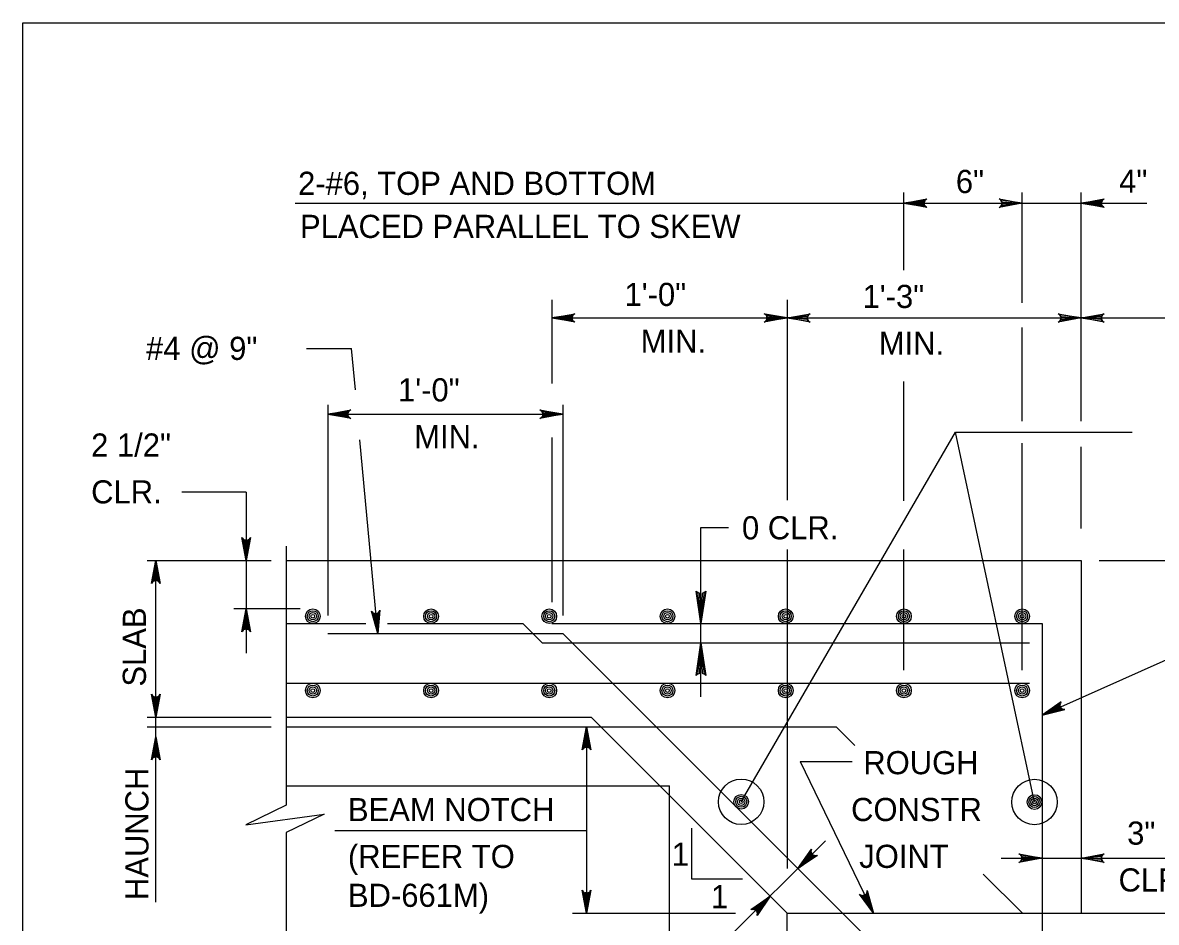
# Model space of a CAD drawing. Extents: x 638653 to 642302, y 298557 to 300414.
# Drawn here: x 639863.2 to 640010, y 299612.9 to 299729.5 of the extents above; entities that cross this region are included whole.
import ezdxf

# ---------------------------------------------------------------- set-up
doc = ezdxf.new("R2010")
doc.units = 0
doc.layers.add('1', color=7, linetype='Continuous')

msp = doc.modelspace()

# ---------------------------------------------------------------- linework, layer by layer
at = {"layer": '1'}
for p, q in [((639863.16, 299165.52), (639863.16, 299729.52)), ((639863.16, 299729.52), (640649.16, 299729.52)), ((639977.33, 299697.45), (639977.33, 299707.5)), ((639992.65, 299693.22), (639992.65, 299707.5)), ((640000.31, 299677.86), (640000.31, 299707.5)), ((639898.47, 299706.12), (640008.81, 299706.12)), ((639931.73, 299693.58), (639931.73, 299682.77)), ((639962.21, 299693.58), (639962.21, 299667.65)), ((639931.73, 299691.25), (639962.21, 299691.25)), ((639962.21, 299691.25), (640000.31, 299691.25)), ((640000.31, 299691.25), (640043.09, 299691.25)), ((639992.65, 299677.86), (639992.65, 299690.01)), ((639899.95, 299687.27), (639905.76, 299687.27)), ((639906.26, 299681.93), (639905.76, 299687.27)), ((639977.33, 299667.55), (639977.33, 299683.03)), ((639902.68, 299679.97), (639902.68, 299652.67)), ((639902.68, 299678.77), (639933.16, 299678.77)), ((639933.16, 299679.97), (639933.16, 299652.67)), ((639931.73, 299675.76), (639931.73, 299654.42)), ((639956.25, 299628.54), (639984.03, 299676.44)), ((639984.03, 299676.44), (640006.89, 299676.44)), ((639994.25, 299628.51), (639984.03, 299676.44)), ((639909.17, 299650.34), (639906.85, 299675.47)), ((639992.65, 299645.6), (639992.65, 299675.01)), ((640000.31, 299663.94), (640000.31, 299674.54)), ((639892.13, 299668.69), (639883.8, 299668.69)), ((639892.13, 299668.69), (639892.13, 299647.79)), ((639951.04, 299642.16), (639951.04, 299664.1)), ((639951.04, 299664.1), (639954.6, 299664.1)), ((639897.28, 299661.67), (639897.28, 299628.08)), ((639962.21, 299661.24), (639962.21, 299619.9)), ((639977.33, 299645.6), (639977.33, 299661.25)), ((639879.3, 299659.83), (639895.34, 299659.83)), ((639880.42, 299639.51), (639880.42, 299659.83)), ((639897.28, 299659.83), (640000.31, 299659.83)), ((640000.31, 299659.83), (640000.31, 299614.11)), ((640002.64, 299659.83), (640021.55, 299659.83)), ((639995.23, 299639.78), (640032.03, 299656.2)), ((639899.13, 299653.54), (639890.52, 299653.54)), ((639897.28, 299651.63), (639907.6, 299651.63)), ((639910.42, 299651.63), (639927.96, 299651.63)), ((639927.96, 299651.63), (639930.47, 299649.12)), ((639931.73, 299651.63), (639995.23, 299651.63)), ((639995.23, 299651.63), (639995.23, 299583.63)), ((639902.68, 299650.34), (639933.16, 299650.34)), ((640005.79, 299577.71), (639933.16, 299650.34)), ((639930.47, 299649.12), (639993.61, 299649.12)), ((639897.28, 299643.91), (639993.61, 299643.91)), ((639879.3, 299639.51), (639895.34, 299639.51)), ((639880.42, 299615.55), (639880.42, 299639.51)), ((639897.28, 299639.51), (639936.81, 299639.51)), ((639962.21, 299614.11), (639936.81, 299639.51)), ((639879.3, 299638.24), (639895.34, 299638.24)), ((639897.28, 299638.24), (639938.08, 299638.24)), ((639936.22, 299638.24), (639936.22, 299614.11)), ((639938.08, 299638.24), (639968.56, 299638.24)), ((639970.97, 299635.82), (639968.56, 299638.24)), ((639963.91, 299633.77), (639973.38, 299614.11)), ((639963.91, 299633.77), (639970.64, 299633.77)), ((639897.28, 299630.62), (639946.97, 299630.62)), ((639946.97, 299546.36), (639946.97, 299630.62)), ((639897.28, 299624.56), (639897.28, 299601.17)), ((639903.6, 299624.82), (639936.22, 299624.82)), ((639949.82, 299625.13), (639949.82, 299618.55)), ((639967.18, 299623.5), (639954.28, 299610.6)), ((639989.93, 299621.24), (640018.92, 299621.24)), ((639949.82, 299618.55), (639956.41, 299618.55)), ((639992.69, 299614.11), (639987.62, 299619.17)), ((639934.38, 299614.11), (639955.53, 299614.11)), ((639962.21, 299614.11), (640000.31, 299614.11)), ((639962.21, 299510.6), (639962.21, 299614.11)), ((640000.31, 299614.11), (640023.17, 299614.11))]:
    msp.add_line(p, q, dxfattribs=at)
for points in [[(639977.33, 299706.12), (639980.32, 299706.68), (639980.2, 299706.6), (639980.09, 299706.52), (639980.03, 299706.42), (639979.97, 299706.32), (639979.95, 299706.22), (639979.93, 299706.12), (639979.95, 299706.02), (639979.97, 299705.92), (639980.03, 299705.82), (639980.09, 299705.72), (639980.2, 299705.64), (639980.32, 299705.56), (639977.33, 299706.12), (639980.2, 299705.64), (639980.09, 299705.72), (639977.33, 299706.12), (639980.03, 299705.82), (639979.97, 299705.92), (639977.33, 299706.12), (639979.95, 299706.02), (639979.93, 299706.12), (639977.33, 299706.12), (639979.95, 299706.22), (639979.97, 299706.32), (639977.33, 299706.12), (639980.03, 299706.42), (639980.09, 299706.52), (639977.33, 299706.12), (639980.2, 299706.6)], [(639992.65, 299706.12), (639989.67, 299705.56), (639989.9, 299705.72), (639990.02, 299705.92), (639990.05, 299706.12), (639990.02, 299706.32), (639989.9, 299706.52), (639989.67, 299706.68), (639992.65, 299706.12), (639989.9, 299706.52), (639990.02, 299706.32), (639992.65, 299706.12), (639990.05, 299706.12), (639990.02, 299705.92), (639992.65, 299706.12), (639989.9, 299705.72)], [(640000.31, 299706.12), (640003.29, 299706.68), (640003.18, 299706.6), (640003.06, 299706.52), (640003, 299706.42), (640002.94, 299706.32), (640002.92, 299706.22), (640002.91, 299706.12), (640002.92, 299706.02), (640002.94, 299705.92), (640003, 299705.82), (640003.06, 299705.72), (640003.18, 299705.64), (640003.29, 299705.56), (640000.31, 299706.12), (640003.18, 299705.64), (640003.06, 299705.72), (640000.31, 299706.12), (640003, 299705.82), (640002.94, 299705.92), (640000.31, 299706.12), (640002.92, 299706.02), (640002.91, 299706.12), (640000.31, 299706.12), (640002.92, 299706.22), (640002.94, 299706.32), (640000.31, 299706.12), (640003, 299706.42), (640003.06, 299706.52), (640000.31, 299706.12), (640003.18, 299706.6)], [(639931.73, 299691.25), (639934.71, 299691.8), (639934.6, 299691.72), (639934.48, 299691.65), (639934.42, 299691.55), (639934.36, 299691.45), (639934.34, 299691.35), (639934.33, 299691.25), (639934.34, 299691.15), (639934.36, 299691.05), (639934.42, 299690.95), (639934.48, 299690.85), (639934.6, 299690.77), (639934.71, 299690.69), (639931.73, 299691.25), (639934.6, 299690.77), (639934.48, 299690.85), (639931.73, 299691.25), (639934.42, 299690.95), (639934.36, 299691.05), (639931.73, 299691.25), (639934.34, 299691.15), (639934.33, 299691.25), (639931.73, 299691.25), (639934.34, 299691.35), (639934.36, 299691.45), (639931.73, 299691.25), (639934.42, 299691.55), (639934.48, 299691.65), (639931.73, 299691.25), (639934.6, 299691.72)], [(639962.21, 299691.25), (639959.22, 299690.69), (639959.34, 299690.77), (639959.45, 299690.85), (639959.51, 299690.95), (639959.57, 299691.05), (639959.59, 299691.15), (639959.61, 299691.25), (639959.59, 299691.35), (639959.57, 299691.45), (639959.51, 299691.55), (639959.45, 299691.65), (639959.34, 299691.72), (639959.22, 299691.8), (639962.21, 299691.25), (639959.34, 299691.72), (639959.45, 299691.65), (639962.21, 299691.25), (639959.51, 299691.55), (639959.57, 299691.45), (639962.21, 299691.25), (639959.59, 299691.35), (639959.61, 299691.25), (639962.21, 299691.25), (639959.59, 299691.15), (639959.57, 299691.05), (639962.21, 299691.25), (639959.51, 299690.95), (639959.45, 299690.85), (639962.21, 299691.25), (639959.34, 299690.77)], [(639962.21, 299691.25), (639965.19, 299691.8), (639964.96, 299691.65), (639964.84, 299691.45), (639964.81, 299691.25), (639964.84, 299691.05), (639964.96, 299690.85), (639965.19, 299690.69), (639962.21, 299691.25), (639964.96, 299690.85), (639964.84, 299691.05), (639962.21, 299691.25), (639964.81, 299691.25), (639964.84, 299691.45), (639962.21, 299691.25), (639964.96, 299691.65)], [(640000.31, 299691.25), (639997.32, 299690.69), (639997.55, 299690.85), (639997.67, 299691.05), (639997.71, 299691.25), (639997.67, 299691.45), (639997.55, 299691.65), (639997.32, 299691.8), (640000.31, 299691.25), (639997.55, 299691.65), (639997.67, 299691.45), (640000.31, 299691.25), (639997.71, 299691.25), (639997.67, 299691.05), (640000.31, 299691.25), (639997.55, 299690.85)], [(640000.31, 299691.25), (640003.29, 299691.8), (640003.06, 299691.65), (640002.94, 299691.45), (640002.91, 299691.25), (640002.94, 299691.05), (640003.06, 299690.85), (640003.29, 299690.69), (640000.31, 299691.25), (640003.06, 299690.85), (640002.94, 299691.05), (640000.31, 299691.25), (640002.91, 299691.25), (640002.94, 299691.45), (640000.31, 299691.25), (640003.06, 299691.65)], [(639902.68, 299678.77), (639905.67, 299679.32), (639905.55, 299679.24), (639905.44, 299679.17), (639905.38, 299679.07), (639905.32, 299678.97), (639905.3, 299678.87), (639905.28, 299678.77), (639905.3, 299678.67), (639905.32, 299678.57), (639905.38, 299678.47), (639905.44, 299678.37), (639905.55, 299678.29), (639905.67, 299678.21), (639902.68, 299678.77), (639905.55, 299678.29), (639905.44, 299678.37), (639902.68, 299678.77), (639905.38, 299678.47), (639905.32, 299678.57), (639902.68, 299678.77), (639905.3, 299678.67), (639905.28, 299678.77), (639902.68, 299678.77), (639905.3, 299678.87), (639905.32, 299678.97), (639902.68, 299678.77), (639905.38, 299679.07), (639905.44, 299679.17), (639902.68, 299678.77), (639905.55, 299679.24)], [(639933.16, 299678.77), (639930.18, 299678.21), (639930.3, 299678.29), (639930.41, 299678.37), (639930.47, 299678.47), (639930.53, 299678.57), (639930.55, 299678.67), (639930.56, 299678.77), (639930.55, 299678.87), (639930.53, 299678.97), (639930.47, 299679.07), (639930.41, 299679.17), (639930.3, 299679.24), (639930.18, 299679.32), (639933.16, 299678.77), (639930.3, 299679.24), (639930.41, 299679.17), (639933.16, 299678.77), (639930.47, 299679.07), (639930.53, 299678.97), (639933.16, 299678.77), (639930.55, 299678.87), (639930.56, 299678.77), (639933.16, 299678.77), (639930.55, 299678.67), (639930.53, 299678.57), (639933.16, 299678.77), (639930.47, 299678.47), (639930.41, 299678.37), (639933.16, 299678.77), (639930.3, 299678.29)], [(639892.13, 299659.83), (639891.57, 299662.81), (639891.65, 299662.69), (639891.73, 299662.58), (639891.83, 299662.52), (639891.93, 299662.46), (639892.03, 299662.44), (639892.13, 299662.43), (639892.23, 299662.44), (639892.33, 299662.46), (639892.43, 299662.52), (639892.53, 299662.58), (639892.61, 299662.69), (639892.69, 299662.81), (639892.13, 299659.83), (639892.61, 299662.69), (639892.53, 299662.58), (639892.13, 299659.83), (639892.43, 299662.52), (639892.33, 299662.46), (639892.13, 299659.83), (639892.23, 299662.44), (639892.13, 299662.43), (639892.13, 299659.83), (639892.03, 299662.44), (639891.93, 299662.46), (639892.13, 299659.83), (639891.83, 299662.52), (639891.73, 299662.58), (639892.13, 299659.83), (639891.65, 299662.69)], [(639880.42, 299659.83), (639880.98, 299656.84), (639880.9, 299656.96), (639880.82, 299657.07), (639880.72, 299657.13), (639880.62, 299657.19), (639880.52, 299657.21), (639880.42, 299657.23), (639880.32, 299657.21), (639880.22, 299657.19), (639880.12, 299657.13), (639880.02, 299657.07), (639879.94, 299656.96), (639879.86, 299656.84), (639880.42, 299659.83), (639879.94, 299656.96), (639880.02, 299657.07), (639880.42, 299659.83), (639880.12, 299657.13), (639880.22, 299657.19), (639880.42, 299659.83), (639880.32, 299657.21), (639880.42, 299657.23), (639880.42, 299659.83), (639880.52, 299657.21), (639880.62, 299657.19), (639880.42, 299659.83), (639880.72, 299657.13), (639880.82, 299657.07), (639880.42, 299659.83), (639880.9, 299656.96)], [(639951.5, 299655.7), (639951.19, 299655.54), (639951.04, 299651.63), (639951.5, 299655.7), (639951.66, 299655.85), (639951.04, 299651.63), (639950.88, 299655.54), (639950.57, 299655.7), (639951.04, 299651.63), (639950.41, 299655.85), (639950.57, 299655.7)], [(639892.13, 299653.54), (639892.69, 299650.56), (639892.61, 299650.67), (639892.53, 299650.79), (639892.43, 299650.85), (639892.33, 299650.91), (639892.23, 299650.92), (639892.13, 299650.94), (639892.03, 299650.92), (639891.93, 299650.91), (639891.83, 299650.85), (639891.73, 299650.79), (639891.65, 299650.67), (639891.57, 299650.56), (639892.13, 299653.54), (639891.65, 299650.67), (639891.73, 299650.79), (639892.13, 299653.54), (639891.83, 299650.85), (639891.93, 299650.91), (639892.13, 299653.54), (639892.03, 299650.92), (639892.13, 299650.94), (639892.13, 299653.54), (639892.23, 299650.92), (639892.33, 299650.91), (639892.13, 299653.54), (639892.43, 299650.85), (639892.53, 299650.79), (639892.13, 299653.54), (639892.61, 299650.67)], [(639909.17, 299650.34), (639908.34, 299653.25), (639908.43, 299653.15), (639908.52, 299653.04), (639908.62, 299652.99), (639908.73, 299652.94), (639908.83, 299652.93), (639908.93, 299652.92), (639909.03, 299652.95), (639909.13, 299652.98), (639909.22, 299653.04), (639909.31, 299653.11), (639909.38, 299653.23), (639909.45, 299653.36), (639909.17, 299650.34), (639909.38, 299653.23), (639909.31, 299653.11), (639909.17, 299650.34), (639909.22, 299653.04), (639909.13, 299652.98), (639909.17, 299650.34), (639909.03, 299652.95), (639908.93, 299652.92), (639909.17, 299650.34), (639908.83, 299652.93), (639908.73, 299652.94), (639909.17, 299650.34), (639908.62, 299652.99), (639908.52, 299653.04), (639909.17, 299650.34), (639908.43, 299653.15)], [(639950.57, 299645.06), (639950.88, 299645.21), (639951.04, 299649.12), (639950.57, 299645.06), (639950.41, 299644.9), (639951.04, 299649.12), (639951.19, 299645.21), (639951.5, 299645.06), (639951.04, 299649.12), (639951.66, 299644.9), (639951.5, 299645.06)], [(639880.42, 299639.51), (639879.86, 299642.49), (639879.94, 299642.37), (639880.02, 299642.26), (639880.12, 299642.2), (639880.22, 299642.14), (639880.32, 299642.12), (639880.42, 299642.11), (639880.52, 299642.12), (639880.62, 299642.14), (639880.72, 299642.2), (639880.82, 299642.26), (639880.9, 299642.37), (639880.98, 299642.49), (639880.42, 299639.51), (639880.9, 299642.37), (639880.82, 299642.26), (639880.42, 299639.51), (639880.72, 299642.2), (639880.62, 299642.14), (639880.42, 299639.51), (639880.52, 299642.12), (639880.42, 299642.11), (639880.42, 299639.51), (639880.32, 299642.12), (639880.22, 299642.14), (639880.42, 299639.51), (639880.12, 299642.2), (639880.02, 299642.26), (639880.42, 299639.51), (639879.94, 299642.37)], [(639995.23, 299639.78), (639998.18, 299640.48), (639998.04, 299640.51), (639997.9, 299640.53), (639997.81, 299640.6), (639997.71, 299640.67), (639997.66, 299640.75), (639997.6, 299640.84), (639997.58, 299640.94), (639997.55, 299641.03), (639997.56, 299641.15), (639997.58, 299641.26), (639997.65, 299641.38), (639997.72, 299641.5), (639995.23, 299639.78), (639997.65, 299641.38), (639997.58, 299641.26), (639995.23, 299639.78), (639997.56, 299641.15), (639997.55, 299641.03), (639995.23, 299639.78), (639997.58, 299640.94), (639997.6, 299640.84), (639995.23, 299639.78), (639997.66, 299640.75), (639997.71, 299640.67), (639995.23, 299639.78), (639997.81, 299640.6), (639997.9, 299640.53), (639995.23, 299639.78), (639998.04, 299640.51)], [(639936.22, 299638.24), (639936.78, 299635.26), (639936.7, 299635.37), (639936.62, 299635.49), (639936.52, 299635.54), (639936.42, 299635.6), (639936.32, 299635.62), (639936.22, 299635.64), (639936.12, 299635.62), (639936.02, 299635.6), (639935.92, 299635.54), (639935.82, 299635.49), (639935.74, 299635.37), (639935.66, 299635.26), (639936.22, 299638.24), (639935.74, 299635.37), (639935.82, 299635.49), (639936.22, 299638.24), (639935.92, 299635.54), (639936.02, 299635.6), (639936.22, 299638.24), (639936.12, 299635.62), (639936.22, 299635.64), (639936.22, 299638.24), (639936.32, 299635.62), (639936.42, 299635.6), (639936.22, 299638.24), (639936.52, 299635.54), (639936.62, 299635.49), (639936.22, 299638.24), (639936.7, 299635.37)], [(639880.42, 299636.97), (639880.98, 299633.98), (639880.9, 299634.1), (639880.82, 299634.21), (639880.72, 299634.27), (639880.62, 299634.33), (639880.52, 299634.35), (639880.42, 299634.37), (639880.32, 299634.35), (639880.22, 299634.33), (639880.12, 299634.27), (639880.02, 299634.21), (639879.94, 299634.1), (639879.86, 299633.98), (639880.42, 299636.97), (639879.94, 299634.1), (639880.02, 299634.21), (639880.42, 299636.97), (639880.12, 299634.27), (639880.22, 299634.33), (639880.42, 299636.97), (639880.32, 299634.35), (639880.42, 299634.37), (639880.42, 299636.97), (639880.52, 299634.35), (639880.62, 299634.33), (639880.42, 299636.97), (639880.72, 299634.27), (639880.82, 299634.21), (639880.42, 299636.97), (639880.9, 299634.1)], [(639897.28, 299628.08), (639892.09, 299625.54), (639902.24, 299626.92), (639897.28, 299624.56)], [(639963.59, 299619.91), (639965.34, 299622.39), (639965.31, 299622.25), (639965.28, 299622.12), (639965.31, 299622), (639965.34, 299621.89), (639965.39, 299621.81), (639965.45, 299621.72), (639965.53, 299621.66), (639965.62, 299621.6), (639965.73, 299621.57), (639965.84, 299621.54), (639965.98, 299621.57), (639966.12, 299621.59), (639963.59, 299619.91), (639965.98, 299621.57), (639965.84, 299621.54), (639963.59, 299619.91), (639965.73, 299621.57), (639965.62, 299621.6), (639963.59, 299619.91), (639965.53, 299621.66), (639965.45, 299621.72), (639963.59, 299619.91), (639965.39, 299621.81), (639965.34, 299621.89), (639963.59, 299619.91), (639965.31, 299622), (639965.28, 299622.12), (639963.59, 299619.91), (639965.31, 299622.25)], [(639995.23, 299621.24), (639992.24, 299620.68), (639992.47, 299620.84), (639992.59, 299621.04), (639992.63, 299621.24), (639992.59, 299621.44), (639992.47, 299621.64), (639992.24, 299621.8), (639995.23, 299621.24), (639992.47, 299621.64), (639992.59, 299621.44), (639995.23, 299621.24), (639992.63, 299621.24), (639992.59, 299621.04), (639995.23, 299621.24), (639992.47, 299620.84)], [(640000.31, 299621.24), (640003.29, 299621.8), (640003.06, 299621.64), (640002.94, 299621.44), (640002.91, 299621.24), (640002.94, 299621.04), (640003.06, 299620.84), (640003.29, 299620.68), (640000.31, 299621.24), (640003.06, 299620.84), (640002.94, 299621.04), (640000.31, 299621.24), (640002.91, 299621.24), (640002.94, 299621.44), (640000.31, 299621.24), (640003.06, 299621.64)], [(639936.22, 299614.11), (639935.66, 299617.09), (639935.74, 299616.97), (639935.82, 299616.86), (639935.92, 299616.8), (639936.02, 299616.74), (639936.12, 299616.72), (639936.22, 299616.71), (639936.32, 299616.72), (639936.42, 299616.74), (639936.52, 299616.8), (639936.62, 299616.86), (639936.7, 299616.97), (639936.78, 299617.09), (639936.22, 299614.11), (639936.7, 299616.97), (639936.62, 299616.86), (639936.22, 299614.11), (639936.52, 299616.8), (639936.42, 299616.74), (639936.22, 299614.11), (639936.32, 299616.72), (639936.22, 299616.71), (639936.22, 299614.11), (639936.12, 299616.72), (639936.02, 299616.74), (639936.22, 299614.11), (639935.92, 299616.8), (639935.82, 299616.86), (639936.22, 299614.11), (639935.74, 299616.97)], [(639973.38, 299614.11), (639971.58, 299616.55), (639971.7, 299616.48), (639971.82, 299616.41), (639971.94, 299616.4), (639972.06, 299616.39), (639972.15, 299616.42), (639972.25, 299616.45), (639972.33, 299616.51), (639972.42, 299616.57), (639972.48, 299616.66), (639972.54, 299616.76), (639972.57, 299616.9), (639972.59, 299617.04), (639973.38, 299614.11), (639972.57, 299616.9), (639972.54, 299616.76), (639973.38, 299614.11), (639972.48, 299616.66), (639972.42, 299616.57), (639973.38, 299614.11), (639972.33, 299616.51), (639972.25, 299616.45), (639973.38, 299614.11), (639972.15, 299616.42), (639972.06, 299616.39), (639973.38, 299614.11), (639971.94, 299616.4), (639971.82, 299616.41), (639973.38, 299614.11), (639971.7, 299616.48)], [(639960, 299616.32), (639958.31, 299613.79), (639958.34, 299613.93), (639958.36, 299614.07), (639958.33, 299614.18), (639958.3, 299614.29), (639958.24, 299614.37), (639958.18, 299614.46), (639958.1, 299614.51), (639958.01, 299614.57), (639957.9, 299614.6), (639957.79, 299614.63), (639957.65, 299614.6), (639957.51, 299614.57), (639960, 299616.32), (639957.65, 299614.6), (639957.79, 299614.63), (639960, 299616.32), (639957.9, 299614.6), (639958.01, 299614.57), (639960, 299616.32), (639958.1, 299614.51), (639958.18, 299614.46), (639960, 299616.32), (639958.24, 299614.37), (639958.3, 299614.29), (639960, 299616.32), (639958.33, 299614.18), (639958.36, 299614.07), (639960, 299616.32), (639958.34, 299613.93)]]:
    msp.add_lwpolyline(points, dxfattribs=at)
for centre, radius in [((639900.75, 299652.59), 0.952), ((639900.75, 299652.59), 0.714), ((639900.75, 299652.59), 0.476), ((639900.75, 299652.59), 0.238), ((639916.07, 299652.59), 0.952), ((639916.07, 299652.59), 0.714), ((639916.07, 299652.59), 0.476), ((639916.07, 299652.59), 0.238), ((639931.38, 299652.59), 0.952), ((639931.38, 299652.59), 0.714), ((639931.38, 299652.59), 0.476), ((639931.38, 299652.59), 0.238), ((639946.7, 299652.59), 0.952), ((639946.7, 299652.59), 0.714), ((639946.7, 299652.59), 0.476), ((639946.7, 299652.59), 0.238), ((639962.02, 299652.59), 0.952), ((639962.02, 299652.59), 0.714), ((639962.02, 299652.59), 0.476), ((639962.02, 299652.59), 0.238), ((639977.33, 299652.59), 0.952), ((639977.33, 299652.59), 0.714), ((639977.33, 299652.59), 0.476), ((639977.33, 299652.59), 0.238), ((639992.65, 299652.59), 0.952), ((639992.65, 299652.59), 0.714), ((639992.65, 299652.59), 0.476), ((639992.65, 299652.59), 0.238), ((639900.75, 299642.96), 0.952), ((639900.75, 299642.96), 0.714), ((639900.75, 299642.96), 0.476), ((639916.07, 299642.96), 0.952), ((639916.07, 299642.96), 0.714), ((639916.07, 299642.96), 0.476), ((639931.38, 299642.96), 0.952), ((639931.38, 299642.96), 0.714), ((639931.38, 299642.96), 0.476), ((639946.7, 299642.96), 0.952), ((639946.7, 299642.96), 0.714), ((639946.7, 299642.96), 0.476), ((639962.02, 299642.96), 0.952), ((639962.02, 299642.96), 0.714), ((639962.02, 299642.96), 0.476), ((639977.33, 299642.96), 0.952), ((639977.33, 299642.96), 0.714), ((639977.33, 299642.96), 0.476), ((639992.65, 299642.96), 0.952), ((639992.65, 299642.96), 0.714), ((639992.65, 299642.96), 0.476), ((639900.75, 299642.96), 0.238), ((639916.07, 299642.96), 0.238), ((639931.38, 299642.96), 0.238), ((639946.7, 299642.96), 0.238), ((639962.02, 299642.96), 0.238), ((639977.33, 299642.96), 0.238), ((639992.65, 299642.96), 0.238), ((639956.25, 299628.54), 2.94), ((639994.25, 299628.51), 2.94), ((639956.25, 299628.54), 0.952), ((639956.25, 299628.54), 0.714), ((639956.25, 299628.54), 0.476), ((639956.25, 299628.54), 0.238), ((639994.25, 299628.51), 0.952), ((639994.25, 299628.51), 0.714), ((639994.25, 299628.51), 0.476), ((639994.25, 299628.51), 0.238)]:
    msp.add_circle(centre, radius, dxfattribs=at)

# ---------------------------------------------------------------- texts
for s, p in [('2-#6, TOP AND BOTTOM', (639898.84, 299707.2)), ('6"', (639984.06, 299707.44)), ('4"', (640005.22, 299707.47)), ('PLACED PARALLEL TO SKEW', (639899.09, 299701.62)), ('1\'-0"', (639941.13, 299692.8)), ('1\'-3"', (639971.97, 299692.54)), ('#4 @ 9"', (639879.15, 299685.81)), ('MIN.', (639943.23, 299686.73)), ('MIN.', (639974.08, 299686.47)), ('1\'-0"', (639911.79, 299680.43)), ('MIN.', (639913.89, 299674.36)), ('2 1/2"', (639872.03, 299673.28)), ('CLR.', (639872.03, 299667.21)), ('0 CLR.', (639956.35, 299662.55)), ('ROUGH', (639972.07, 299632.11)), ('BEAM NOTCH', (639905.3, 299626.03)), ('CONSTR', (639970.49, 299626.04)), (' 3"', (640005.14, 299622.98)), ('(REFER TO', (639905.3, 299619.96)), ('1', (639947.26, 299620.25)), (' JOINT', (639970.43, 299619.97)), ('CLR.', (640005.14, 299616.91)), ('BD-661M)', (639905.3, 299614.92)), ('1', (639952.32, 299614.74))]:
    msp.add_text(s, height=3, dxfattribs=at).set_placement(p)
for s, p in [('SLAB', (639879.13, 299643.47)), ('HAUNCH', (639879.46, 299615.8))]:
    msp.add_text(s, height=3, rotation=90, dxfattribs=at).set_placement(p)

doc.saveas('drawing.dxf')
